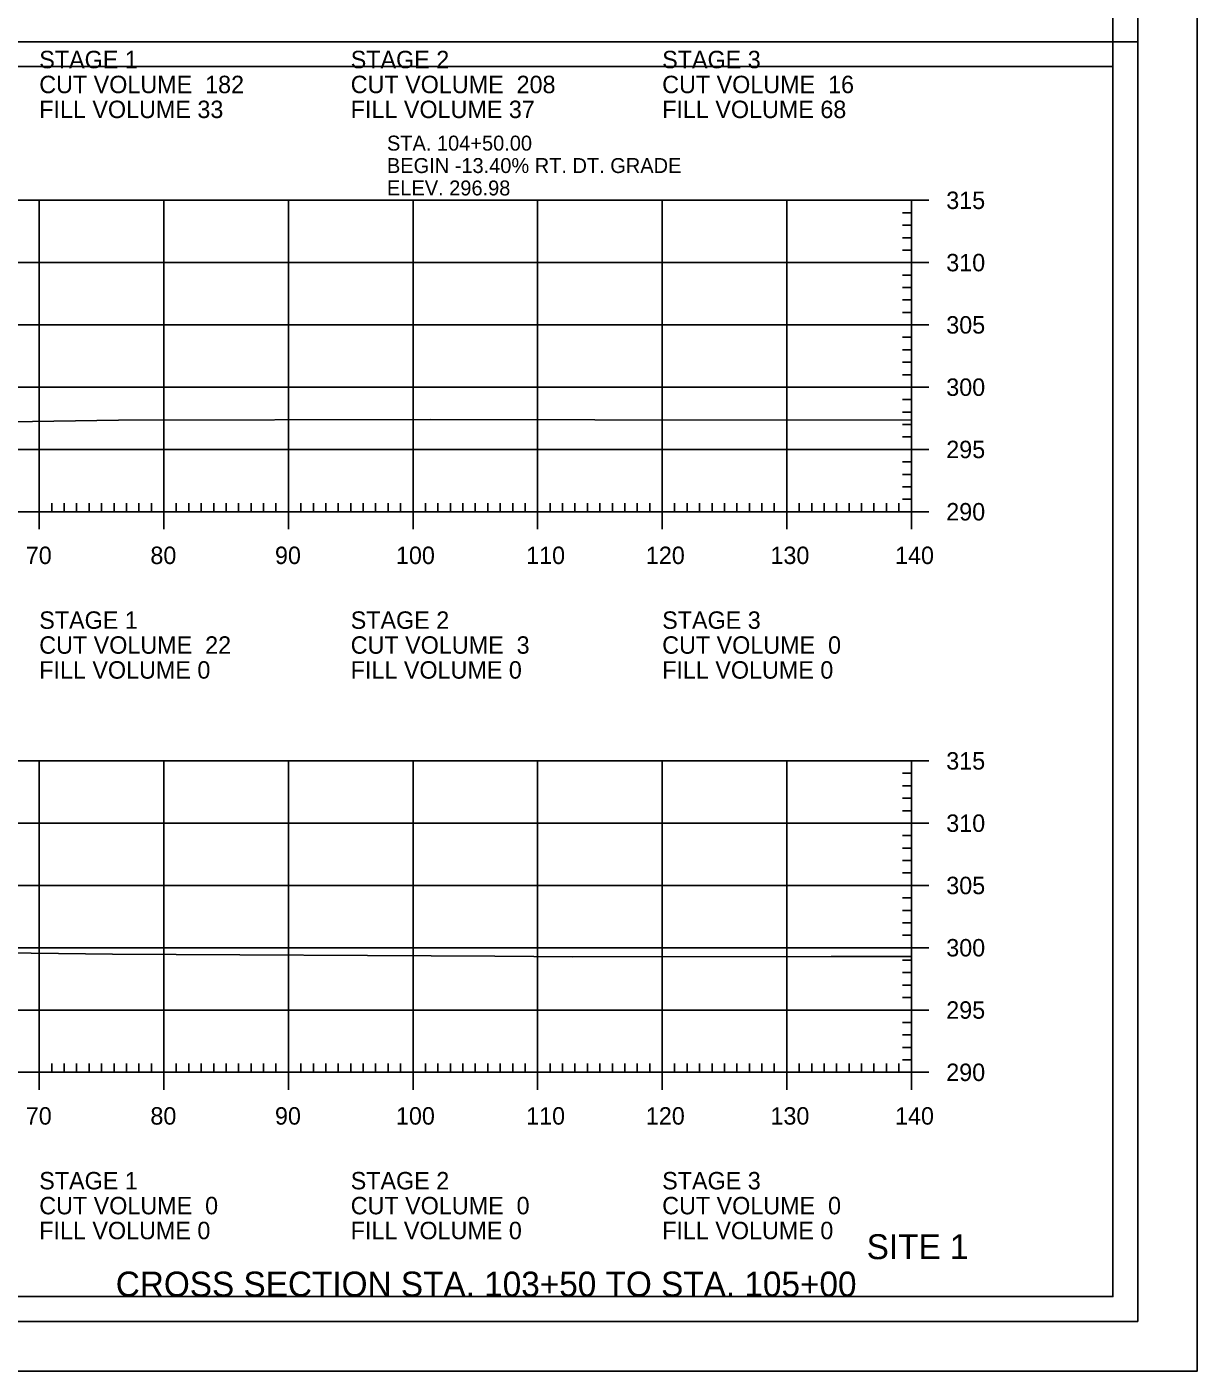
# Model space of a CAD drawing. Extents: x 1368713 to 1370673, y 380279 to 380950.
# Drawn here: x 1370221.3 to 1370315.2, y 380310.4 to 380418.3 of the extents above; entities that cross this region are included whole.
import ezdxf

# ---------------------------------------------------------------- set-up
doc = ezdxf.new("R2010")
doc.units = 0
for name, color, linetype in [('Notes', 7, 'Continuous'), ('R_Axis', 7, 'Continuous'), ('R_Axis Annot', 7, 'Continuous'), ('R_Border', 7, 'Continuous'), ('R_Border Plan-Plan', 7, 'Continuous'), ('R_Draft', 7, 'Continuous'), ('R_Exist Surface', 7, 'Continuous'), ('R_Grid', 7, 'Continuous'), ('R_No Plot', 7, 'Continuous')]:
    doc.layers.add(name, color=color, linetype=linetype)

msp = doc.modelspace()

# ---------------------------------------------------------------- linework, layer by layer
at = {"layer": 'R_Axis'}
for p, q in [((1370293.68, 380404.42), (1370290.88, 380404.42)), ((1370292.28, 380379.42), (1370292.28, 380404.42)), ((1370292.28, 380403.42), (1370291.58, 380403.42)), ((1370292.28, 380402.42), (1370291.58, 380402.42)), ((1370292.28, 380401.42), (1370291.58, 380401.42)), ((1370292.28, 380400.42), (1370291.58, 380400.42)), ((1370293.68, 380399.42), (1370290.88, 380399.42)), ((1370292.28, 380398.42), (1370291.58, 380398.42)), ((1370292.28, 380397.42), (1370291.58, 380397.42)), ((1370292.28, 380396.42), (1370291.58, 380396.42)), ((1370292.28, 380395.42), (1370291.58, 380395.42)), ((1370293.68, 380394.42), (1370290.88, 380394.42)), ((1370292.28, 380393.42), (1370291.58, 380393.42)), ((1370292.28, 380392.42), (1370291.58, 380392.42)), ((1370292.28, 380391.42), (1370291.58, 380391.42)), ((1370292.28, 380390.42), (1370291.58, 380390.42)), ((1370293.68, 380389.42), (1370290.88, 380389.42)), ((1370292.28, 380388.42), (1370291.58, 380388.42)), ((1370292.28, 380387.42), (1370291.58, 380387.42)), ((1370292.28, 380386.42), (1370291.58, 380386.42)), ((1370292.28, 380385.42), (1370291.58, 380385.42)), ((1370293.68, 380384.42), (1370290.88, 380384.42)), ((1370292.28, 380383.42), (1370291.58, 380383.42)), ((1370292.28, 380382.42), (1370291.58, 380382.42)), ((1370292.28, 380381.42), (1370291.58, 380381.42)), ((1370222.28, 380378.02), (1370222.28, 380380.82)), ((1370232.28, 380378.02), (1370232.28, 380380.82)), ((1370242.28, 380378.02), (1370242.28, 380380.82)), ((1370252.28, 380378.02), (1370252.28, 380380.82)), ((1370262.28, 380378.02), (1370262.28, 380380.82)), ((1370272.28, 380378.02), (1370272.28, 380380.82)), ((1370282.28, 380378.02), (1370282.28, 380380.82)), ((1370292.28, 380380.42), (1370291.58, 380380.42)), ((1370292.28, 380378.02), (1370292.28, 380380.82)), ((1370012.28, 380379.42), (1370292.28, 380379.42)), ((1370223.28, 380379.42), (1370223.28, 380380.12)), ((1370224.28, 380379.42), (1370224.28, 380380.12)), ((1370225.28, 380379.42), (1370225.28, 380380.12)), ((1370226.28, 380379.42), (1370226.28, 380380.12)), ((1370227.28, 380379.42), (1370227.28, 380380.12)), ((1370228.28, 380379.42), (1370228.28, 380380.12)), ((1370229.28, 380379.42), (1370229.28, 380380.12)), ((1370230.28, 380379.42), (1370230.28, 380380.12)), ((1370231.28, 380379.42), (1370231.28, 380380.12)), ((1370233.28, 380379.42), (1370233.28, 380380.12)), ((1370234.28, 380379.42), (1370234.28, 380380.12)), ((1370235.28, 380379.42), (1370235.28, 380380.12)), ((1370236.28, 380379.42), (1370236.28, 380380.12)), ((1370237.28, 380379.42), (1370237.28, 380380.12)), ((1370238.28, 380379.42), (1370238.28, 380380.12)), ((1370239.28, 380379.42), (1370239.28, 380380.12)), ((1370240.28, 380379.42), (1370240.28, 380380.12)), ((1370241.28, 380379.42), (1370241.28, 380380.12)), ((1370243.28, 380379.42), (1370243.28, 380380.12)), ((1370244.28, 380379.42), (1370244.28, 380380.12)), ((1370245.28, 380379.42), (1370245.28, 380380.12)), ((1370246.28, 380379.42), (1370246.28, 380380.12)), ((1370247.28, 380379.42), (1370247.28, 380380.12)), ((1370248.28, 380379.42), (1370248.28, 380380.12)), ((1370249.28, 380379.42), (1370249.28, 380380.12)), ((1370250.28, 380379.42), (1370250.28, 380380.12)), ((1370251.28, 380379.42), (1370251.28, 380380.12)), ((1370253.28, 380379.42), (1370253.28, 380380.12)), ((1370254.28, 380379.42), (1370254.28, 380380.12)), ((1370255.28, 380379.42), (1370255.28, 380380.12)), ((1370256.28, 380379.42), (1370256.28, 380380.12)), ((1370257.28, 380379.42), (1370257.28, 380380.12)), ((1370258.28, 380379.42), (1370258.28, 380380.12)), ((1370259.28, 380379.42), (1370259.28, 380380.12)), ((1370260.28, 380379.42), (1370260.28, 380380.12)), ((1370261.28, 380379.42), (1370261.28, 380380.12)), ((1370263.28, 380379.42), (1370263.28, 380380.12)), ((1370264.28, 380379.42), (1370264.28, 380380.12)), ((1370265.28, 380379.42), (1370265.28, 380380.12)), ((1370266.28, 380379.42), (1370266.28, 380380.12)), ((1370267.28, 380379.42), (1370267.28, 380380.12)), ((1370268.28, 380379.42), (1370268.28, 380380.12)), ((1370269.28, 380379.42), (1370269.28, 380380.12)), ((1370270.28, 380379.42), (1370270.28, 380380.12)), ((1370271.28, 380379.42), (1370271.28, 380380.12)), ((1370273.28, 380379.42), (1370273.28, 380380.12)), ((1370274.28, 380379.42), (1370274.28, 380380.12)), ((1370275.28, 380379.42), (1370275.28, 380380.12)), ((1370276.28, 380379.42), (1370276.28, 380380.12)), ((1370277.28, 380379.42), (1370277.28, 380380.12)), ((1370278.28, 380379.42), (1370278.28, 380380.12)), ((1370279.28, 380379.42), (1370279.28, 380380.12)), ((1370280.28, 380379.42), (1370280.28, 380380.12)), ((1370281.28, 380379.42), (1370281.28, 380380.12)), ((1370283.28, 380379.42), (1370283.28, 380380.12)), ((1370284.28, 380379.42), (1370284.28, 380380.12)), ((1370285.28, 380379.42), (1370285.28, 380380.12)), ((1370286.28, 380379.42), (1370286.28, 380380.12)), ((1370287.28, 380379.42), (1370287.28, 380380.12)), ((1370288.28, 380379.42), (1370288.28, 380380.12)), ((1370289.28, 380379.42), (1370289.28, 380380.12)), ((1370290.28, 380379.42), (1370290.28, 380380.12)), ((1370293.68, 380379.42), (1370290.88, 380379.42)), ((1370291.28, 380379.42), (1370291.28, 380380.12)), ((1370293.68, 380359.42), (1370290.88, 380359.42)), ((1370292.28, 380334.42), (1370292.28, 380359.42)), ((1370292.28, 380358.42), (1370291.58, 380358.42)), ((1370292.28, 380357.42), (1370291.58, 380357.42)), ((1370292.28, 380356.42), (1370291.58, 380356.42)), ((1370293.68, 380354.42), (1370290.88, 380354.42)), ((1370292.28, 380355.42), (1370291.58, 380355.42)), ((1370292.28, 380353.42), (1370291.58, 380353.42)), ((1370292.28, 380352.42), (1370291.58, 380352.42)), ((1370292.28, 380351.42), (1370291.58, 380351.42)), ((1370292.28, 380350.42), (1370291.58, 380350.42)), ((1370293.68, 380349.42), (1370290.88, 380349.42)), ((1370292.28, 380348.42), (1370291.58, 380348.42)), ((1370292.28, 380347.42), (1370291.58, 380347.42)), ((1370292.28, 380346.42), (1370291.58, 380346.42)), ((1370292.28, 380345.42), (1370291.58, 380345.42)), ((1370293.68, 380344.42), (1370290.88, 380344.42)), ((1370292.28, 380343.42), (1370291.58, 380343.42)), ((1370292.28, 380342.42), (1370291.58, 380342.42)), ((1370292.28, 380341.42), (1370291.58, 380341.42)), ((1370292.28, 380340.42), (1370291.58, 380340.42)), ((1370293.68, 380339.42), (1370290.88, 380339.42)), ((1370292.28, 380338.42), (1370291.58, 380338.42)), ((1370292.28, 380337.42), (1370291.58, 380337.42)), ((1370292.28, 380336.42), (1370291.58, 380336.42)), ((1370222.28, 380333.02), (1370222.28, 380335.82)), ((1370223.28, 380334.42), (1370223.28, 380335.12)), ((1370224.28, 380334.42), (1370224.28, 380335.12)), ((1370225.28, 380334.42), (1370225.28, 380335.12)), ((1370226.28, 380334.42), (1370226.28, 380335.12)), ((1370227.28, 380334.42), (1370227.28, 380335.12)), ((1370228.28, 380334.42), (1370228.28, 380335.12)), ((1370229.28, 380334.42), (1370229.28, 380335.12)), ((1370230.28, 380334.42), (1370230.28, 380335.12)), ((1370231.28, 380334.42), (1370231.28, 380335.12)), ((1370232.28, 380333.02), (1370232.28, 380335.82)), ((1370233.28, 380334.42), (1370233.28, 380335.12)), ((1370234.28, 380334.42), (1370234.28, 380335.12)), ((1370235.28, 380334.42), (1370235.28, 380335.12)), ((1370236.28, 380334.42), (1370236.28, 380335.12)), ((1370237.28, 380334.42), (1370237.28, 380335.12)), ((1370238.28, 380334.42), (1370238.28, 380335.12)), ((1370239.28, 380334.42), (1370239.28, 380335.12)), ((1370240.28, 380334.42), (1370240.28, 380335.12)), ((1370241.28, 380334.42), (1370241.28, 380335.12)), ((1370242.28, 380333.02), (1370242.28, 380335.82)), ((1370243.28, 380334.42), (1370243.28, 380335.12)), ((1370244.28, 380334.42), (1370244.28, 380335.12)), ((1370245.28, 380334.42), (1370245.28, 380335.12)), ((1370246.28, 380334.42), (1370246.28, 380335.12)), ((1370247.28, 380334.42), (1370247.28, 380335.12)), ((1370248.28, 380334.42), (1370248.28, 380335.12)), ((1370249.28, 380334.42), (1370249.28, 380335.12)), ((1370250.28, 380334.42), (1370250.28, 380335.12)), ((1370251.28, 380334.42), (1370251.28, 380335.12)), ((1370252.28, 380333.02), (1370252.28, 380335.82)), ((1370253.28, 380334.42), (1370253.28, 380335.12)), ((1370254.28, 380334.42), (1370254.28, 380335.12)), ((1370255.28, 380334.42), (1370255.28, 380335.12)), ((1370256.28, 380334.42), (1370256.28, 380335.12)), ((1370257.28, 380334.42), (1370257.28, 380335.12)), ((1370258.28, 380334.42), (1370258.28, 380335.12)), ((1370259.28, 380334.42), (1370259.28, 380335.12)), ((1370260.28, 380334.42), (1370260.28, 380335.12)), ((1370261.28, 380334.42), (1370261.28, 380335.12)), ((1370262.28, 380333.02), (1370262.28, 380335.82)), ((1370263.28, 380334.42), (1370263.28, 380335.12)), ((1370264.28, 380334.42), (1370264.28, 380335.12)), ((1370265.28, 380334.42), (1370265.28, 380335.12)), ((1370266.28, 380334.42), (1370266.28, 380335.12)), ((1370267.28, 380334.42), (1370267.28, 380335.12)), ((1370268.28, 380334.42), (1370268.28, 380335.12)), ((1370269.28, 380334.42), (1370269.28, 380335.12)), ((1370270.28, 380334.42), (1370270.28, 380335.12)), ((1370271.28, 380334.42), (1370271.28, 380335.12)), ((1370272.28, 380333.02), (1370272.28, 380335.82)), ((1370273.28, 380334.42), (1370273.28, 380335.12)), ((1370274.28, 380334.42), (1370274.28, 380335.12)), ((1370275.28, 380334.42), (1370275.28, 380335.12)), ((1370276.28, 380334.42), (1370276.28, 380335.12)), ((1370277.28, 380334.42), (1370277.28, 380335.12)), ((1370278.28, 380334.42), (1370278.28, 380335.12)), ((1370279.28, 380334.42), (1370279.28, 380335.12)), ((1370280.28, 380334.42), (1370280.28, 380335.12)), ((1370281.28, 380334.42), (1370281.28, 380335.12)), ((1370282.28, 380333.02), (1370282.28, 380335.82)), ((1370283.28, 380334.42), (1370283.28, 380335.12)), ((1370284.28, 380334.42), (1370284.28, 380335.12)), ((1370285.28, 380334.42), (1370285.28, 380335.12)), ((1370286.28, 380334.42), (1370286.28, 380335.12)), ((1370287.28, 380334.42), (1370287.28, 380335.12)), ((1370288.28, 380334.42), (1370288.28, 380335.12)), ((1370289.28, 380334.42), (1370289.28, 380335.12)), ((1370290.28, 380334.42), (1370290.28, 380335.12)), ((1370291.28, 380334.42), (1370291.28, 380335.12)), ((1370292.28, 380335.42), (1370291.58, 380335.42)), ((1370292.28, 380333.02), (1370292.28, 380335.82)), ((1370012.28, 380334.42), (1370292.28, 380334.42)), ((1370293.68, 380334.42), (1370290.88, 380334.42))]:
    msp.add_line(p, q, dxfattribs=at)
at = {"layer": 'R_Border'}
for q in [(1370310.46, 380519.88), (1369994.28, 380314.42)]:
    msp.add_line((1370310.46, 380314.42), q, dxfattribs=at)
at = {"layer": 'R_Border Plan-Plan'}
msp.add_line((1369994.28, 380417.15), (1370310.46, 380417.15), dxfattribs=at)
at = {"layer": 'R_Exist Surface'}
for points in [[(1370128.18, 380390.61), (1370131.25, 380390.58), (1370134.22, 380390.7), (1370134.8, 380390.72), (1370141.93, 380390.9), (1370146.06, 380390.91), (1370152.14, 380390.9), (1370156.26, 380390.87), (1370162.69, 380390.84), (1370163.85, 380390.84), (1370164.72, 380390.84), (1370172.18, 380390.29), (1370177.37, 380389.92), (1370184, 380388.97), (1370199.24, 380386.42), (1370204.44, 380386.39), (1370228.63, 380386.76), (1370253.7, 380386.83), (1370266.87, 380386.8), (1370292.28, 380386.76)], [(1370199.87, 380344.26), (1370228.17, 380343.91), (1370258.85, 380343.75), (1370265.1, 380343.7), (1370285.83, 380343.72), (1370291.77, 380343.72), (1370292.28, 380343.72)]]:
    msp.add_lwpolyline(points, dxfattribs=at)
at = {"layer": 'R_Grid'}
for p, q in [((1370012.28, 380404.42), (1370292.28, 380404.42)), ((1370222.28, 380379.42), (1370222.28, 380404.42)), ((1370232.28, 380379.42), (1370232.28, 380404.42)), ((1370242.28, 380379.42), (1370242.28, 380404.42)), ((1370252.28, 380379.42), (1370252.28, 380404.42)), ((1370262.28, 380379.42), (1370262.28, 380404.42)), ((1370272.28, 380379.42), (1370272.28, 380404.42)), ((1370282.28, 380379.42), (1370282.28, 380404.42)), ((1370292.28, 380379.42), (1370292.28, 380404.42)), ((1370012.28, 380399.42), (1370292.28, 380399.42)), ((1370012.28, 380394.42), (1370292.28, 380394.42)), ((1370012.28, 380389.42), (1370292.28, 380389.42)), ((1370012.28, 380384.42), (1370292.28, 380384.42)), ((1370012.28, 380379.42), (1370292.28, 380379.42)), ((1370012.28, 380359.42), (1370292.28, 380359.42)), ((1370222.28, 380334.42), (1370222.28, 380359.42)), ((1370232.28, 380334.42), (1370232.28, 380359.42)), ((1370242.28, 380334.42), (1370242.28, 380359.42)), ((1370252.28, 380334.42), (1370252.28, 380359.42)), ((1370262.28, 380334.42), (1370262.28, 380359.42)), ((1370272.28, 380334.42), (1370272.28, 380359.42)), ((1370282.28, 380334.42), (1370282.28, 380359.42)), ((1370292.28, 380334.42), (1370292.28, 380359.42)), ((1370012.28, 380354.42), (1370292.28, 380354.42)), ((1370012.28, 380349.42), (1370292.28, 380349.42)), ((1370012.28, 380344.42), (1370292.28, 380344.42)), ((1370012.28, 380339.42), (1370292.28, 380339.42)), ((1370012.28, 380334.42), (1370292.28, 380334.42))]:
    msp.add_line(p, q, dxfattribs=at)
at = {"layer": 'R_No Plot'}
for points in [[(1369981.88, 380523.77), (1370315.22, 380523.77), (1370315.22, 380310.43), (1369981.88, 380310.43)], [(1369996.28, 380517.88), (1370245.82, 380517.88), (1370245.82, 380508), (1370263.36, 380508), (1370287.46, 380508), (1370287.46, 380485.66), (1370308.46, 380485.66), (1370308.46, 380316.42), (1369996.28, 380316.42)], [(1369996.28, 380415.15), (1370308.46, 380415.15), (1370308.46, 380316.42), (1369996.28, 380316.42)]]:
    msp.add_lwpolyline(points, close=True, dxfattribs=at)

# ---------------------------------------------------------------- texts
at = {"layer": 'Notes'}
for s, p in [('STA. 104+50.00', (1370250.19, 380408.41)), ('BEGIN -13.40% RT. DT. GRADE', (1370250.19, 380406.61)), ('ELEV. 296.98', (1370250.19, 380404.81))]:
    msp.add_text(s, height=1.2, dxfattribs=at).set_placement(p)
at = {"layer": 'R_Axis Annot'}
for s, p in [('STAGE 1', (1370222.28, 380415.02)), ('STAGE 2', (1370247.28, 380415.02)), ('STAGE 3', (1370272.28, 380415.02)), ('CUT VOLUME  182', (1370222.28, 380413.02)), ('CUT VOLUME  208', (1370247.28, 380413.02)), ('CUT VOLUME  16', (1370272.28, 380413.02)), ('FILL VOLUME 33', (1370222.28, 380411.02)), ('FILL VOLUME 37', (1370247.28, 380411.02)), ('FILL VOLUME 68', (1370272.28, 380411.02)), ('315', (1370295.08, 380403.72)), ('310', (1370295.08, 380398.72)), ('305', (1370295.08, 380393.72)), ('300', (1370295.08, 380388.72)), ('295', (1370295.08, 380383.72)), ('290', (1370295.08, 380378.72)), ('70', (1370221.2, 380375.22)), ('80', (1370231.2, 380375.22)), ('90', (1370241.2, 380375.22)), ('100', (1370250.91, 380375.22)), ('110', (1370261.36, 380375.22)), ('120', (1370270.97, 380375.22)), ('130', (1370280.97, 380375.22)), ('140', (1370290.97, 380375.22)), ('STAGE 1', (1370222.28, 380370.02)), ('STAGE 2', (1370247.28, 380370.02)), ('STAGE 3', (1370272.28, 380370.02)), ('CUT VOLUME  22', (1370222.28, 380368.02)), ('CUT VOLUME  3', (1370247.28, 380368.02)), ('CUT VOLUME  0', (1370272.28, 380368.02)), ('FILL VOLUME 0', (1370222.28, 380366.02)), ('FILL VOLUME 0', (1370247.28, 380366.02)), ('FILL VOLUME 0', (1370272.28, 380366.02)), ('315', (1370295.08, 380358.72)), ('310', (1370295.08, 380353.72)), ('305', (1370295.08, 380348.72)), ('300', (1370295.08, 380343.72)), ('295', (1370295.08, 380338.72)), ('290', (1370295.08, 380333.72)), ('70', (1370221.2, 380330.22)), ('80', (1370231.2, 380330.22)), ('90', (1370241.2, 380330.22)), ('100', (1370250.91, 380330.22)), ('110', (1370261.36, 380330.22)), ('120', (1370270.97, 380330.22)), ('130', (1370280.97, 380330.22)), ('140', (1370290.97, 380330.22)), ('STAGE 1', (1370222.28, 380325.02)), ('STAGE 2', (1370247.28, 380325.02)), ('STAGE 3', (1370272.28, 380325.02)), ('CUT VOLUME  0', (1370222.28, 380323.02)), ('CUT VOLUME  0', (1370247.28, 380323.02)), ('CUT VOLUME  0', (1370272.28, 380323.02)), ('FILL VOLUME 0', (1370222.28, 380321.02)), ('FILL VOLUME 0', (1370247.28, 380321.02)), ('FILL VOLUME 0', (1370272.28, 380321.02))]:
    msp.add_text(s, height=1.4, dxfattribs=at).set_placement(p)
at = {"layer": 'R_Draft'}
for s, p in [('SITE 1', (1370288.69, 380319.42)), ('CROSS SECTION STA. 103+50 TO STA. 105+00', (1370228.42, 380316.42))]:
    msp.add_text(s, height=2, dxfattribs=at).set_placement(p)

doc.saveas('drawing.dxf')
